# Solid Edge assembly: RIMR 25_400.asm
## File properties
Title: Zylinder
Author: ahadarics
Template: iso metric assembly.asm
Last saved by: ahadarics
Revision: 16
Application: Solid Edge
Username: ahadarics
Dokumentum tartalom típus: 1
Document Number: RIMR 25/400
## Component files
Profilrohr.par
Kolbenstange.par
Kit_1.par
Kit_2.par
Mutter_1.par
Mutter_2.par
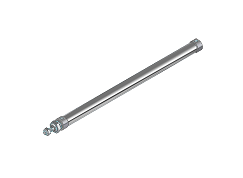
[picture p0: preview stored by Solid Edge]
